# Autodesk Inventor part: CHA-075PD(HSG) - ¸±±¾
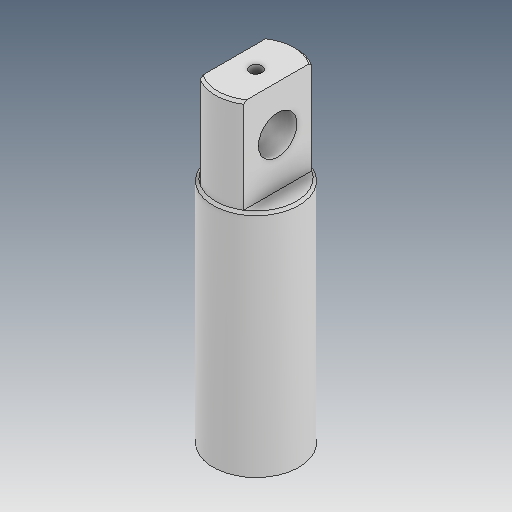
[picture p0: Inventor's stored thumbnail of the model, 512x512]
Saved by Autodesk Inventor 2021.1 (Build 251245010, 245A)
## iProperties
Created: 2021-05
Part Number: CHA-075PD(HSG) - ¸±±¾
Material: Ogólny
Document SubType Name: Modeling
Designer: user
Density: 1 g/cm^3
Appearance: Domyślna
Author: user
Revision Number: ÈÎºÎ
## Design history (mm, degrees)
feature "M6 ÂÝÎÆ¿×1"
node "Bryła1"
